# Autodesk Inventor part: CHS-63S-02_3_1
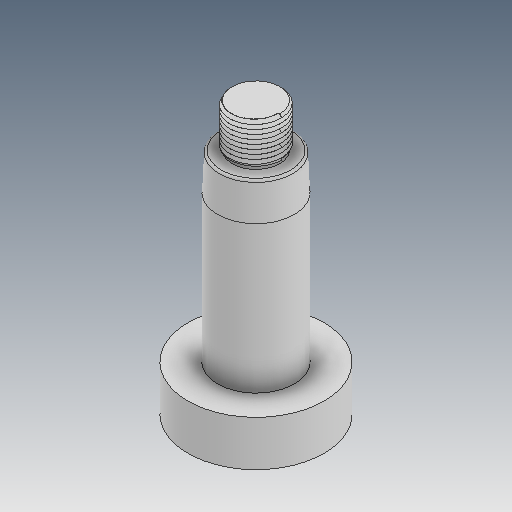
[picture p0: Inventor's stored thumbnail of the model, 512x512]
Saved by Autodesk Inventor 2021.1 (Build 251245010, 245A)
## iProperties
Created: 2019-05
Part Number: CHS-63S-02_3_1
Material: Ogólny
Document SubType Name: Modeling
Designer: user
Density: 1 g/cm^3
Appearance: Domyślna
Author: user
Revision Number: ÈÎºÎ
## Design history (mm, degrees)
feature "ÊäÈë1"
feature "ÊäÈë2"
node "Bryła1"
node "Bryła2"
